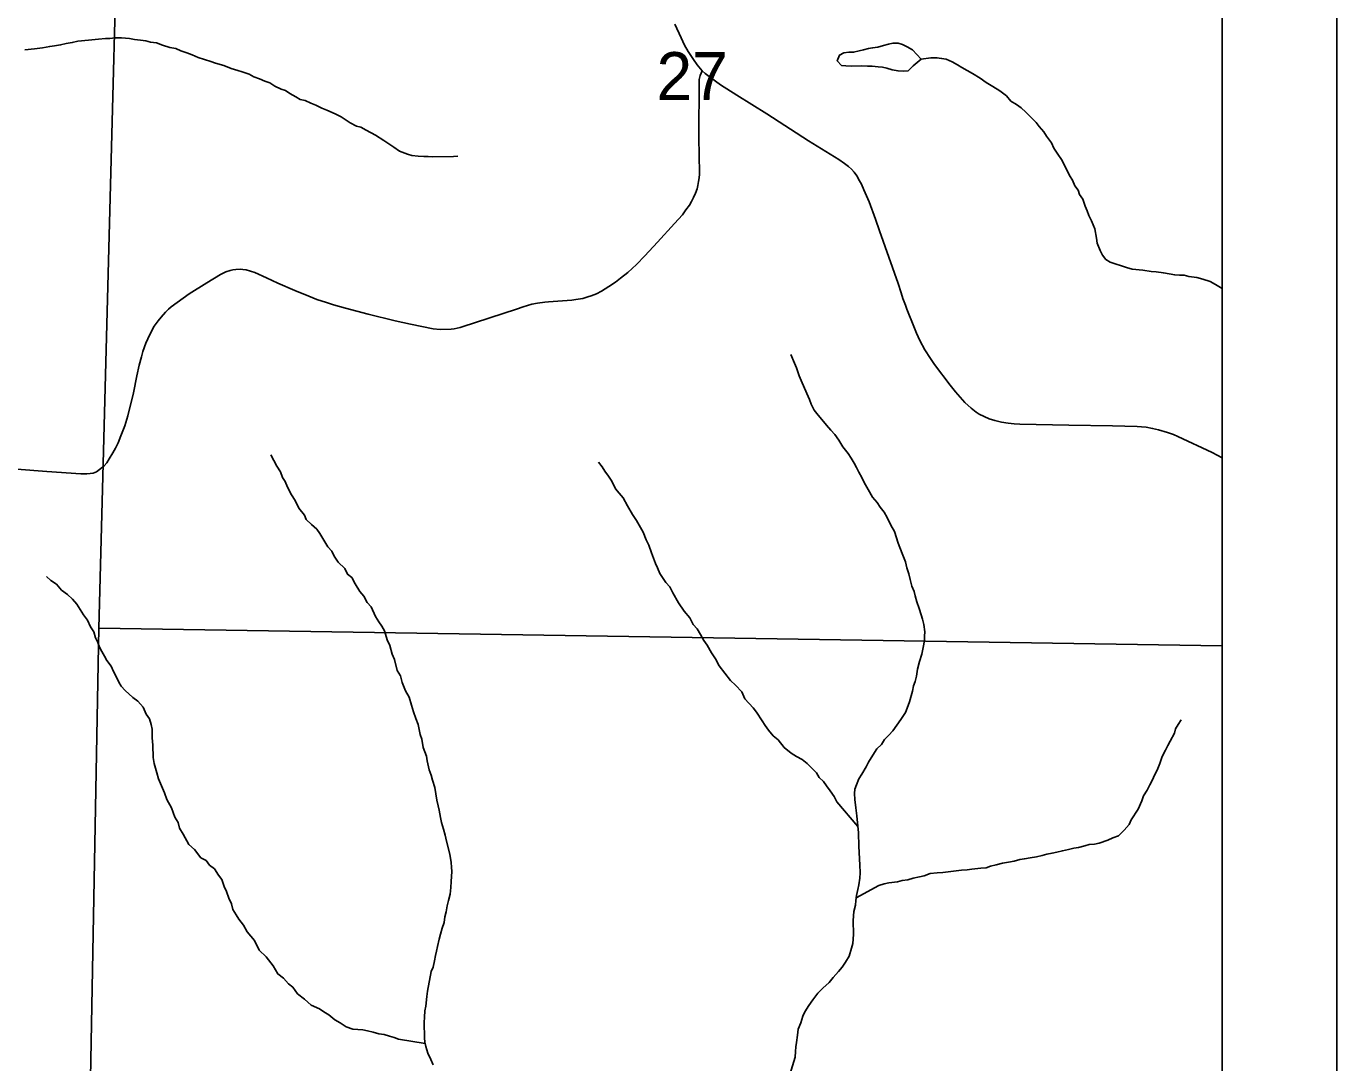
# Model space of a CAD drawing. Extents: x 0 to 34, y -8.9 to 22.
# Drawn here: x 29.472 to 30.617, y 7.79 to 8.695 of the extents above; entities that cross this region are included whole.
import ezdxf

# ---------------------------------------------------------------- set-up
doc = ezdxf.new("R2010")
doc.units = 0
for name, color, linetype in [('GM_X_Corporation', 7, 'Continuous'), ('GM_X_County_Road', 7, 'Continuous'), ('GM_X_Minor_River', 7, 'Continuous'), ('GM_X_Section_Text', 7, 'Continuous'), ('GM_X_Township_Road', 7, 'Continuous'), ('SH_Data', 7, 'Continuous')]:
    doc.layers.add(name, color=color, linetype=linetype)

msp = doc.modelspace()

# ---------------------------------------------------------------- linework, layer by layer
at = {"layer": 'GM_X_Corporation'}
for points in [[(28.7046, 7.104), (30.5167, 7.104), (30.5167, 13.904), (28.8143, 13.904), (28.8122, 13.7561), (28.8049, 13.053), (28.7787, 12.0377), (28.7786, 12.0342), (28.7779, 11.9899), (28.7762, 11.8872), (28.7797, 11.7437), (28.7775, 11.7346), (28.7754, 11.6346), (28.7651, 11.3014), (28.7622, 11.1187), (28.7609, 11.0119), (28.7377, 10.2012), (28.7308, 9.4444), (28.7238, 9.1729), (28.7123, 8.2818)], [(28.7046, 7.104), (30.5167, 7.104), (30.5167, 12.0118), (29.364, 12.0313), (29.2718, 12.0324), (28.9225, 12.0359), (28.8128, 12.0371), (28.7787, 12.0377), (28.7786, 12.0342), (28.7779, 11.9899), (28.7762, 11.8872), (28.7797, 11.7437), (28.7775, 11.7346), (28.7754, 11.6346), (28.7651, 11.3014), (28.7622, 11.1187), (28.7609, 11.0119), (28.7377, 10.2012), (28.7308, 9.4444), (28.7238, 9.1729), (28.7123, 8.2818)], [(30.5167, 8.1537), (30.5167, 9.1586), (29.562, 9.1756), (29.5357, 8.1691)], [(30.5167, 7.1326), (30.5167, 8.1537), (29.5357, 8.1691), (29.5168, 7.1478)]]:
    msp.add_lwpolyline(points, close=True, dxfattribs=at)
at = {"layer": 'GM_X_County_Road'}
msp.add_lwpolyline([(30.5167, 8.318), (30.5077, 8.3225), (30.4779, 8.3366), (30.4741, 8.3382), (30.4689, 8.34), (30.461, 8.3424), (30.4558, 8.3436), (30.4501, 8.3446), (30.4462, 8.3451), (30.4424, 8.3453), (30.4208, 8.3459), (30.3826, 8.3465), (30.34, 8.3474), (30.3349, 8.3476), (30.3297, 8.3482), (30.3239, 8.3492), (30.3181, 8.3505), (30.3132, 8.3521), (30.3086, 8.354), (30.3044, 8.3561), (30.3018, 8.3579), (30.2974, 8.3613), (30.2918, 8.3663), (30.2838, 8.3755), (30.2789, 8.3815), (30.2655, 8.3995), (30.2619, 8.4047), (30.257, 8.4122), (30.2526, 8.4205), (30.2496, 8.4269), (30.2472, 8.4327), (30.2413, 8.4478), (30.24, 8.4512), (30.2378, 8.4572), (30.2362, 8.4621), (30.2335, 8.4701), (30.2174, 8.5163), (30.2137, 8.5265), (30.2082, 8.5414), (30.2037, 8.5521), (30.2015, 8.5568), (30.1999, 8.5599), (30.1974, 8.5643), (30.1952, 8.5674), (30.1929, 8.57), (30.1902, 8.5723), (30.1868, 8.575), (30.1817, 8.5784), (30.1552, 8.5949), (30.1188, 8.6185), (30.0927, 8.6346), (30.0786, 8.6438), (30.0696, 8.6502), (30.0652, 8.6536), (30.0624, 8.6558), (30.0582, 8.6611), (30.0549, 8.6657), (30.0502, 8.6728), (30.0471, 8.6784), (30.044, 8.6847), (30.0385, 8.6967)], dxfattribs=at)
at = {"layer": 'GM_X_Minor_River'}
for points in [[(29.4709, 8.6742), (29.4795, 8.6751), (29.4863, 8.676), (29.4927, 8.6772), (29.4969, 8.6777), (29.5022, 8.6785), (29.5071, 8.6797), (29.5124, 8.6806), (29.5173, 8.6818), (29.5267, 8.6827), (29.5354, 8.6836), (29.5414, 8.6841), (29.5452, 8.6842), (29.5498, 8.6847), (29.5554, 8.6848), (29.5623, 8.6841)], [(29.5623, 8.6841), (29.5668, 8.6834), (29.5721, 8.6828), (29.5767, 8.6821), (29.5808, 8.681), (29.5858, 8.6804), (29.5911, 8.6782), (29.5976, 8.6764), (29.6029, 8.6754), (29.6071, 8.6735), (29.6124, 8.6717), (29.617, 8.6699), (29.6223, 8.6677), (29.628, 8.6659), (29.6334, 8.6641), (29.6375, 8.6627), (29.6448, 8.6605), (29.6512, 8.658), (29.657, 8.6562), (29.6608, 8.6551), (29.6668, 8.653), (29.671, 8.6508), (29.676, 8.649), (29.6806, 8.6468), (29.6848, 8.6453), (29.6894, 8.6424), (29.6947, 8.6398), (29.6985, 8.6387), (29.7023, 8.6362), (29.7077, 8.6332), (29.7115, 8.631), (29.7157, 8.63), (29.7206, 8.6278), (29.7252, 8.626), (29.7302, 8.6234), (29.7347, 8.6216), (29.742, 8.6183), (29.7473, 8.6157), (29.755, 8.6106), (29.7607, 8.6076), (29.7645, 8.6066), (29.7691, 8.604), (29.7771, 8.5996), (29.7844, 8.5952), (29.7932, 8.5892), (29.7982, 8.5859), (29.805, 8.583), (29.8088, 8.5819), (29.8145, 8.5813), (29.8195, 8.581), (29.8232, 8.5811), (29.827, 8.5807), (29.8452, 8.5811), (29.849, 8.5815)], [(30.2537, 8.6661), (30.2468, 8.6602), (30.2423, 8.6559), (30.2382, 8.6555), (30.2336, 8.6558), (30.2283, 8.6568), (30.2237, 8.6583), (30.2199, 8.659), (30.2162, 8.6593), (30.2108, 8.6599), (30.2067, 8.6599), (30.2018, 8.6602), (30.1927, 8.66), (30.1878, 8.6603), (30.184, 8.6606), (30.1805, 8.6647), (30.1823, 8.6697), (30.1861, 8.6716), (30.1906, 8.6721), (30.1947, 8.6722), (30.1996, 8.6734), (30.2034, 8.6742), (30.2076, 8.6754), (30.2113, 8.6759), (30.2159, 8.6767), (30.2208, 8.6779), (30.2253, 8.6791), (30.229, 8.68), (30.2336, 8.6801), (30.2374, 8.679), (30.2416, 8.6768), (30.2462, 8.6742), (30.2537, 8.6661)], [(30.2537, 8.6661), (30.2622, 8.6673), (30.2675, 8.6674), (30.2716, 8.6667), (30.2754, 8.666), (30.2808, 8.6638), (30.2854, 8.6613), (30.2892, 8.6587), (30.2984, 8.6535), (30.3052, 8.6495), (30.3106, 8.6458), (30.3163, 8.6421), (30.3225, 8.6384), (30.3282, 8.634), (30.3321, 8.6295), (30.3371, 8.6265), (30.3409, 8.6236), (30.3451, 8.6199), (30.349, 8.6161), (30.354, 8.6109), (30.3567, 8.6072), (30.3609, 8.6027), (30.3633, 8.5989), (30.3675, 8.593), (30.3695, 8.5884), (30.3726, 8.5839), (30.3769, 8.5776), (30.3832, 8.5644), (30.3859, 8.5603), (30.3879, 8.5554), (30.3909, 8.5517), (30.3921, 8.5479), (30.3949, 8.5438), (30.3969, 8.5377), (30.3988, 8.5336), (30.4, 8.5295), (30.4024, 8.525), (30.4055, 8.5178), (30.4068, 8.5099), (30.4073, 8.5053), (30.41, 8.4989), (30.412, 8.4948), (30.4151, 8.4911), (30.4189, 8.4889), (30.433, 8.4842), (30.4379, 8.4827), (30.4474, 8.4818), (30.4546, 8.4808), (30.4588, 8.4805), (30.4652, 8.4794), (30.4751, 8.4777), (30.4793, 8.4774), (30.4834, 8.4775), (30.4876, 8.4764), (30.4944, 8.4754), (30.4998, 8.474), (30.5062, 8.4718), (30.5108, 8.4693), (30.5167, 8.4658)], [(30.1399, 8.4081), (30.1431, 8.4006), (30.1447, 8.3964), (30.1471, 8.3896), (30.149, 8.3855), (30.1538, 8.3742), (30.1561, 8.369), (30.1577, 8.3648), (30.1604, 8.3596), (30.1639, 8.3551), (30.167, 8.3513), (30.1709, 8.3465), (30.1747, 8.342), (30.1782, 8.3383), (30.1817, 8.3334), (30.1852, 8.3274), (30.1899, 8.3218), (30.1926, 8.3177), (30.1953, 8.3132), (30.1973, 8.3094), (30.1992, 8.3053), (30.2019, 8.3008), (30.2039, 8.2963), (30.2074, 8.2902), (30.2113, 8.2835), (30.2152, 8.279), (30.2179, 8.2749), (30.2214, 8.2704), (30.2241, 8.2659), (30.2273, 8.2591), (30.2304, 8.2535), (30.2336, 8.2433), (30.2352, 8.2396), (30.2376, 8.2328), (30.2399, 8.2271), (30.2412, 8.2219), (30.2428, 8.2166), (30.244, 8.2117), (30.2456, 8.206), (30.2476, 8.2011), (30.2484, 8.1973), (30.25, 8.1921), (30.252, 8.1864), (30.2536, 8.1808), (30.2548, 8.177), (30.256, 8.1725), (30.2569, 8.166), (30.2566, 8.1622), (30.2566, 8.1584), (30.2556, 8.1524), (30.2542, 8.1466), (30.2524, 8.1402), (30.2506, 8.1333), (30.2496, 8.1272), (30.2486, 8.1227), (30.2471, 8.1188), (30.246, 8.1143), (30.2436, 8.1048), (30.2414, 8.0994), (30.2399, 8.0956), (30.2359, 8.0895), (30.2289, 8.0795), (30.2255, 8.0756), (30.2218, 8.0718), (30.2192, 8.0676), (30.2151, 8.0637), (30.2115, 8.0583), (30.2078, 8.0522), (30.2056, 8.048), (30.2019, 8.0418), (30.1993, 8.0376), (30.1971, 8.0323), (30.1957, 8.0285), (30.1954, 8.0247), (30.1959, 8.0194), (30.1967, 8.0122), (30.1976, 8.0054), (30.1981, 7.9993), (30.199, 7.9906), (30.1992, 7.9785), (30.1997, 7.9736), (30.1998, 7.9675), (30.2002, 7.9626), (30.2004, 7.9554), (30.2001, 7.9508), (30.1994, 7.9451), (30.1983, 7.9409), (30.1973, 7.9356), (30.1966, 7.9314), (30.1963, 7.9273), (30.1949, 7.9216), (30.1943, 7.914), (30.1945, 7.9015), (30.1939, 7.8939), (30.1928, 7.8897), (30.1907, 7.8828), (30.1877, 7.8775), (30.1848, 7.8732), (30.1814, 7.8694), (30.177, 7.864), (30.1733, 7.8598)], [(29.6859, 8.3205), (29.691, 8.3107), (29.6941, 8.3058), (29.696, 8.3009), (29.6984, 8.2972), (29.7003, 8.2923), (29.7039, 8.2855), (29.707, 8.2807), (29.7101, 8.2739), (29.7152, 8.2679), (29.7167, 8.2642), (29.7213, 8.2597), (29.726, 8.2556), (29.7287, 8.2519), (29.7357, 8.2402), (29.7392, 8.2365), (29.7411, 8.232), (29.7446, 8.2267), (29.7504, 8.2212), (29.7527, 8.2163), (29.7566, 8.2133), (29.7593, 8.208), (29.7636, 8.2013), (29.7671, 8.1972), (29.7698, 8.1915), (29.7733, 8.1878), (29.7772, 8.1795), (29.78, 8.1747), (29.7827, 8.1709), (29.785, 8.1668), (29.7874, 8.1589), (29.7898, 8.154), (29.7918, 8.1464), (29.7938, 8.1419), (29.7962, 8.1321), (29.7989, 8.1276), (29.8006, 8.1216), (29.8033, 8.1144), (29.8065, 8.1088), (29.8085, 8.102), (29.8105, 8.096), (29.8125, 8.0903), (29.8144, 8.0851), (29.8161, 8.0764), (29.8177, 8.0722), (29.8189, 8.065), (29.8217, 8.0575), (29.8222, 8.0533), (29.8242, 8.0454), (29.8258, 8.0409), (29.827, 8.0364), (29.829, 8.03), (29.8307, 8.019), (29.8319, 8.0141), (29.8328, 8.0103), (29.834, 8.0039), (29.8348, 7.9994), (29.8365, 7.9937), (29.8381, 7.9884), (29.8393, 7.9831), (29.8421, 7.9718), (29.8434, 7.9646), (29.8435, 7.9605), (29.8439, 7.9567), (29.8433, 7.948), (29.843, 7.9426), (29.8424, 7.9369), (29.8409, 7.9312), (29.8399, 7.9267), (29.8388, 7.9213), (29.8378, 7.9172), (29.8371, 7.9122), (29.8353, 7.9073), (29.8339, 7.9019), (29.8328, 7.8977), (29.8314, 7.8913), (29.8304, 7.8871), (29.8297, 7.8833), (29.8286, 7.8787), (29.8276, 7.873), (29.8257, 7.8692), (29.8226, 7.8521), (29.822, 7.8475), (29.821, 7.8391), (29.8203, 7.835), (29.82, 7.8293), (29.8197, 7.8247), (29.8199, 7.8115), (29.8204, 7.8077), (29.8212, 7.8039), (29.8228, 7.7979), (29.8256, 7.7926), (29.8275, 7.7877)], [(29.972, 8.3141), (29.9751, 8.31), (29.9775, 8.3063), (29.9806, 8.3018), (29.9837, 8.2977), (29.9868, 8.2909), (29.9899, 8.2872), (29.9934, 8.2831), (29.9973, 8.2759), (30.0016, 8.2684), (30.0051, 8.2632), (30.0086, 8.2572), (30.0109, 8.253), (30.0137, 8.2463), (30.016, 8.2418), (30.0181, 8.235), (30.0216, 8.2256), (30.0236, 8.2218), (30.0256, 8.2169), (30.0306, 8.209), (30.0341, 8.2053), (30.0368, 8.2), (30.0419, 8.1914), (30.0466, 8.1839), (30.0516, 8.1783), (30.0547, 8.1723), (30.0582, 8.1686), (30.0609, 8.1637), (30.064, 8.1584), (30.0668, 8.1543), (30.0707, 8.1476), (30.0742, 8.1423), (30.0773, 8.1363), (30.0873, 8.1236), (30.0916, 8.1195), (30.097, 8.1135), (30.0997, 8.1075), (30.1071, 8.0997), (30.1098, 8.0959), (30.1148, 8.0881), (30.1175, 8.0843), (30.1203, 8.0802), (30.1245, 8.075), (30.1287, 8.0716), (30.1341, 8.0649), (30.1403, 8.0601), (30.1449, 8.0571), (30.1498, 8.0546), (30.1541, 8.0509), (30.1583, 8.0468), (30.1622, 8.0427), (30.1645, 8.0389), (30.1683, 8.0352), (30.171, 8.0314), (30.1742, 8.027), (30.1776, 8.0221), (30.18, 8.0176), (30.1984, 7.9961)], [(29.4898, 8.2143), (29.4936, 8.2109), (29.4986, 8.2076), (29.5029, 8.2024), (29.5082, 8.1987), (29.5125, 8.1946), (29.5163, 8.1901), (29.5194, 8.1856), (29.5222, 8.1807), (29.5257, 8.1763), (29.5284, 8.1702), (29.5311, 8.1661), (29.5327, 8.1608), (29.5347, 8.1567), (29.5363, 8.1526), (29.5382, 8.1488), (29.5406, 8.1447), (29.5425, 8.1409), (29.5464, 8.1361), (29.5484, 8.1312), (29.5507, 8.127), (29.5531, 8.1221), (29.555, 8.1184), (29.5585, 8.1147), (29.5654, 8.1087), (29.5696, 8.1054), (29.5743, 8.1002), (29.577, 8.0941), (29.5797, 8.09), (29.5813, 8.0851), (29.5822, 8.081), (29.5823, 8.0734), (29.5828, 8.0669), (29.583, 8.0563), (29.5838, 8.051), (29.5862, 8.0427), (29.5878, 8.0375), (29.5902, 8.0314), (29.593, 8.0254), (29.595, 8.0194), (29.5989, 8.0123), (29.602, 8.004), (29.6048, 7.9995), (29.606, 7.9946), (29.6091, 7.9893), (29.6142, 7.9803), (29.6192, 7.9759), (29.6246, 7.9687), (29.6292, 7.9662), (29.6323, 7.9621), (29.6365, 7.9591), (29.64, 7.9535), (29.6431, 7.9497), (29.6451, 7.9437), (29.6471, 7.9392), (29.6491, 7.9335), (29.6514, 7.9283), (29.6526, 7.9234), (29.6554, 7.9189), (29.6577, 7.9151), (29.662, 7.9099), (29.6651, 7.9039), (29.6716, 7.8964), (29.6756, 7.8881), (29.6817, 7.8822), (29.6879, 7.8743), (29.6918, 7.8672), (29.6968, 7.8635), (29.7011, 7.8586), (29.7049, 7.8557), (29.7092, 7.8497), (29.7153, 7.8452), (29.7211, 7.84), (29.7283, 7.8368), (29.7321, 7.8342), (29.7363, 7.8316), (29.7417, 7.8271), (29.7463, 7.8246), (29.7517, 7.8209), (29.7574, 7.8191), (29.7661, 7.8185), (29.7703, 7.8174), (29.7752, 7.8164), (29.7801, 7.8149), (29.7847, 7.8142), (29.7893, 7.8128), (29.7934, 7.8117), (29.7972, 7.8103), (29.8206, 7.8065)], [(30.4807, 8.0892), (30.4781, 8.085), (30.4759, 8.0812), (30.4749, 8.0774), (30.4712, 8.0705), (30.469, 8.0667), (30.4672, 8.0625), (30.4642, 8.0571), (30.4621, 8.051), (30.4599, 8.0453), (30.4577, 8.0414), (30.4555, 8.0361), (30.4533, 8.0323), (30.4511, 8.0277), (30.4478, 8.0227), (30.4464, 8.0185), (30.4431, 8.0112), (30.4372, 8.0017), (30.4354, 7.9978), (30.4309, 7.9928), (30.4261, 7.9878), (30.4212, 7.9862), (30.4167, 7.9839), (30.4092, 7.9815), (30.405, 7.9806), (30.4005, 7.9802), (30.3967, 7.979), (30.3911, 7.9777), (30.3869, 7.9769), (30.3824, 7.976), (30.3771, 7.9748), (30.3722, 7.9736), (30.3681, 7.9728), (30.3635, 7.9719), (30.3594, 7.9707), (30.3545, 7.9695), (30.3488, 7.9686), (30.3439, 7.9678), (30.3398, 7.967), (30.3349, 7.9657), (30.33, 7.9649), (30.3247, 7.964), (30.3191, 7.9624), (30.3142, 7.9612), (30.3104, 7.96), (30.3059, 7.9595), (30.2979, 7.9586), (30.2938, 7.9582), (30.2889, 7.9577), (30.2726, 7.9559), (30.2677, 7.9554), (30.2617, 7.955), (30.2564, 7.953), (30.2523, 7.9521), (30.2466, 7.9509), (30.2421, 7.9493), (30.2372, 7.9488), (30.233, 7.9476), (30.2255, 7.9467), (30.2213, 7.9459), (30.2168, 7.9443), (30.197, 7.9338)], [(30.1733, 7.8598), (30.1677, 7.8547), (30.1636, 7.8505), (30.1592, 7.8447), (30.1555, 7.8397), (30.1521, 7.834), (30.1503, 7.8302), (30.1485, 7.8244), (30.1464, 7.8191), (30.1457, 7.8138), (30.1447, 7.8073), (30.1444, 7.8035), (30.144, 7.7994), (30.1438, 7.7944), (29.9774, 7.2542)]]:
    msp.add_lwpolyline(points, dxfattribs=at)
at = {"layer": 'GM_X_Township_Road'}
msp.add_lwpolyline([(29.464, 8.3079), (29.4903, 8.306), (29.52, 8.3041), (29.5251, 8.304), (29.5279, 8.3042), (29.5307, 8.3046), (29.5335, 8.3058), (29.5363, 8.3078), (29.5401, 8.3109), (29.5425, 8.3137), (29.5447, 8.317), (29.5478, 8.3222), (29.55, 8.3263), (29.5524, 8.3311), (29.5549, 8.3371), (29.5582, 8.3459), (29.5608, 8.3547), (29.5658, 8.3748), (29.5689, 8.3895), (29.5709, 8.3988), (29.5727, 8.4061), (29.5741, 8.4109), (29.5767, 8.4182), (29.5783, 8.422), (29.581, 8.4275), (29.584, 8.4328), (29.5873, 8.4375), (29.5899, 8.4408), (29.5938, 8.4452), (29.5965, 8.4478), (29.5987, 8.4498), (29.6145, 8.4613), (29.6299, 8.4709), (29.6417, 8.478), (29.6436, 8.479), (29.6464, 8.4803), (29.6502, 8.4815), (29.6526, 8.4821), (29.6551, 8.4824), (29.6594, 8.4826), (29.6613, 8.4825), (29.6642, 8.4821), (29.668, 8.4811), (29.6718, 8.4797), (29.6819, 8.4752), (29.6919, 8.4706), (29.7068, 8.464), (29.7189, 8.459), (29.7261, 8.4563), (29.7343, 8.4535), (29.7405, 8.4515), (29.751, 8.4485), (29.7709, 8.4433), (29.7944, 8.4376), (29.8077, 8.4348), (29.8275, 8.4307), (29.8338, 8.43), (29.8433, 8.4303), (29.846, 8.4307), (29.8512, 8.4319), (29.8528, 8.4324), (29.9003, 8.4478), (29.906, 8.4498), (29.9137, 8.452), (29.9186, 8.453), (29.9251, 8.454), (29.9283, 8.4543), (29.9485, 8.4556), (29.9521, 8.4561), (29.9583, 8.4572), (29.9625, 8.4584), (29.9655, 8.4594), (29.9701, 8.4613), (29.9745, 8.4635), (29.981, 8.4675), (29.9867, 8.4714), (29.9912, 8.4747), (29.9975, 8.4797), (30.005, 8.4869), (30.0123, 8.4944), (30.0236, 8.5063), (30.0382, 8.5225), (30.0452, 8.5303), (30.0483, 8.5345), (30.0513, 8.5387), (30.0532, 8.5418), (30.055, 8.5452), (30.0567, 8.549), (30.058, 8.553), (30.0587, 8.5559), (30.0594, 8.5594), (30.0598, 8.5626), (30.06, 8.5658), (30.0599, 8.5832), (30.0595, 8.5966), (30.0598, 8.6483), (30.0608, 8.6518), (30.0624, 8.6558)], dxfattribs=at)
at = {"layer": 'SH_Data'}
for points in [[(23.6167, 14.004), (30.6167, 14.004), (30.6167, 7.004), (23.6167, 7.004)], [(23.7167, 13.904), (30.5167, 13.904), (30.5167, 7.104), (23.7167, 7.104)]]:
    msp.add_lwpolyline(points, close=True, dxfattribs=at)

# ---------------------------------------------------------------- texts
at = {"layer": 'GM_X_Section_Text'}
msp.add_text('27', height=0.04186, rotation=0, dxfattribs=at).set_placement((30.0226, 8.6304))

doc.saveas('drawing.dxf')
